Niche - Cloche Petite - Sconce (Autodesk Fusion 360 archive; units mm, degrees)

design "Elongated Sconce - Cloche Petite" references "Cloche Petite", "Elongated Sconce - Helio"
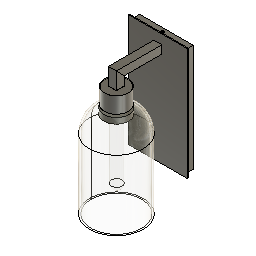
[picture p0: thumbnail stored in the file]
external_derived "ExternalDerived1" bodies "Socket Cover", "T9-Bulb", "Screw Bottom", "Knurled Shade Ring", "Screw Top", "Back Plate", "Sconce", "Socket - E26"
derived_instance "DerivedInstance1"
derived_instance "DerivedInstance2"
derived_instance "DerivedInstance3"
derived_instance "DerivedInstance4"
derived_instance "DerivedInstance5"
derived_instance "DerivedInstance6"
derived_instance "DerivedInstance7"
derived_instance "DerivedInstance8"
derived_instance "DerivedInstance9"
external_derived "ExternalDerived2" bodies "Cloche Petite"
align "Align1"
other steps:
derived_base_feature "Derived Base Feature1" bodies "Socket Cover"
derived_base_feature "Derived Base Feature1" bodies "T9-Bulb"
derived_base_feature "Derived Base Feature1" bodies "Screw Bottom"
derived_base_feature "Derived Base Feature1" bodies "Knurled Shade Ring"
derived_base_feature "Derived Base Feature1" bodies "Screw Top"
derived_base_feature "Derived Base Feature1" bodies "Back Plate"
derived_base_feature "Derived Base Feature1" bodies "Sconce"
derived_base_feature "Derived Base Feature1" bodies "Socket - E26"
derived_base_feature "Derived Base Feature1" bodies "E26 Base"
derived_base_feature "Derived Base Feature2" bodies "Cloche Petite"
create_component "CreateComponent1"
create_component "CreateComponent2"
create_component "CreateComponent3"
create_component "CreateComponent4"
create_component "CreateComponent5"
create_component "CreateComponent6"
create_component "CreateComponent7"
create_component "CreateComponent8"
create_component "CreateComponent9"
named bodies: "Back Plate", "Screw Top", "Knurled Shade Ring", "Sconce", "Cloche Petite", "Socket Cover", "Screw Bottom", "Socket - E26", "T9-Bulb", "E26 Base"

design "Cloche Petite"
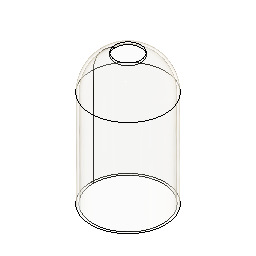
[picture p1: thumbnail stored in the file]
named bodies: "Cloche Petite"

design "Elongated Sconce - Helio"
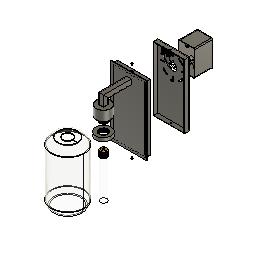
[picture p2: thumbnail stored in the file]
derived_base_feature "Derived Base Feature1" bodies "T9-Bulb", "Helio"
derived_base_feature "Derived Base Feature2" bodies "Back Plate", "Socket Cover", "Screw Top", "Screw Bottom", "Knurled Shade Ring", "Socket - E26"
derived_base_feature "Derived Base Feature3" bodies "E26 Base"
move "Move1"
component_from_bodies "Body->Comp1"
component_from_bodies "Body->Comp2"
component_from_bodies "Body->Comp3"
component_from_bodies "Body->Comp4"
component_from_bodies "Body->Comp5"
component_from_bodies "Body->Comp6"
component_from_bodies "Body->Comp7"
component_from_bodies "Body->Comp8"
component_from_bodies "Body->Comp9"
component_from_bodies "Body->Comp10"
derived_base_feature "Derived Base Feature5" bodies "screw1", "screw1 (1)", "Body1"
move "Move3"
move "Move4"
move "Move5"
move "Move6"
component_from_bodies "Body->Comp11"
component_from_bodies "Body->Comp12"
component_from_bodies "Body->Comp13"
component_from_bodies "Body->Comp14"
component_from_bodies "Body->Comp15"
component_from_bodies "Body->Comp16"
component_from_bodies "Body->Comp17"
component_from_bodies "Body->Comp18"
component_from_bodies "Body->Comp19"
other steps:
base_feature "Base Feature1" bodies "T9-Bulb"
base_feature "Base Feature1" bodies "E26 Base"
base_feature "Base Feature1" bodies "Body1"
base_feature "Base Feature1" bodies "Body1 (1) (1)"
base_feature "Base Feature1" bodies "Body9"
base_feature "Base Feature1" bodies "Body7"
base_feature "Base Feature1" bodies "Body6"
base_feature "Base Feature1" bodies "screw1"
base_feature "Base Feature1" bodies "Body4"
base_feature "Base Feature1" bodies "screw1 (1)"
base_feature "Base Feature1" bodies "Body1 (1)"
base_feature "Base Feature1" bodies "Helio"
base_feature "Base Feature1" bodies "Back Plate"
base_feature "Base Feature1" bodies "Knurled Shade Ring"
base_feature "Base Feature1" bodies "Screw Top"
base_feature "Base Feature1" bodies "Sconce"
base_feature "Base Feature1" bodies "Socket Cover"
base_feature "Base Feature1" bodies "Screw Bottom"
base_feature "Base Feature1" bodies "Socket - E26"
create_component "CreateComponent1"
remove_body "RemoveBody1"
create_component "CreateComponent2"
remove_body "RemoveBody2"
create_component "CreateComponent3"
remove_body "RemoveBody3"
create_component "CreateComponent4"
remove_body "RemoveBody4"
create_component "CreateComponent5"
remove_body "RemoveBody5"
create_component "CreateComponent6"
remove_body "RemoveBody6"
create_component "CreateComponent7"
remove_body "RemoveBody7"
create_component "CreateComponent8"
remove_body "RemoveBody8"
create_component "CreateComponent9"
remove_body "RemoveBody9"
create_component "CreateComponent10"
remove_body "RemoveBody10"
create_component "CreateComponent11"
remove_body "RemoveBody11"
create_component "CreateComponent12"
remove_body "RemoveBody12"
create_component "CreateComponent13"
remove_body "RemoveBody13"
create_component "CreateComponent14"
remove_body "RemoveBody14"
create_component "CreateComponent15"
remove_body "RemoveBody15"
create_component "CreateComponent16"
remove_body "RemoveBody16"
create_component "CreateComponent17"
remove_body "RemoveBody17"
create_component "CreateComponent18"
remove_body "RemoveBody18"
create_component "CreateComponent19"
remove_body "RemoveBody19"
named bodies: "T9-Bulb", "Helio", "Back Plate", "Socket Cover", "Screw Top", "Screw Bottom", "Knurled Shade Ring", "Socket - E26", "Body34", "Sconce", "E26 Base", "screw1", "screw1 (1)", "Body1", "Body1 (1)", "Body4", "Body6", "Body7", "Body1 (1) (1)", "Body9"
